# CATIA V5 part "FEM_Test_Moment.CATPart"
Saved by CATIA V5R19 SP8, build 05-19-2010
Part number: Part1
Material "Stahl": density 7860 kg/m3, Young's modulus 1e+16 Pa, Poisson ratio 0.266, thermal expansion 1.17e-05 1/K
Bounding box of the stored display mesh (mm): x -5 to 5, y 0 to 100, z -60 to 60
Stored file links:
  C:\Users\Bernd\Desktop\FEM_Test_Moment.CATPart
  C:\CATIA_V5_R19\Dassault Systemes\B19\intel_a\startup\materials\German\Catalog.CATMaterial
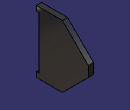
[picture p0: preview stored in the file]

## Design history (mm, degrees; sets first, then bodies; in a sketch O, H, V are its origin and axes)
AxisSystem1: origin (0, 0, 0), X (1, 0, 0), Y (0, 1, 0), Z (0, 0, 1)
Body1 (main body), material "Stahl"
  Sketch1 on YZ plane of AxisSystem1, origin (0, 0, 0), H (0, 1, 0), V (0, 0, 1)
    point P1 (50, 0)
    line L1 (100, 60) -> (100, -60)
    line L2 (100, -60) -> (0, -60)
    line L3 (0, -60) -> (0, 60)
    line L4 (0, 60) -> (100, 60)
    point P5 (0, 60)
    length L4 = 100
    length L1 = 120
    vertical: L1 V, L3 V
    horizontal: L2 H, L4 H
    equidistance: L1 L3 P1, L2 L4 P1
    coincidence: P5 V, P1 H
  Pad1: profile Sketch1, direction (1, 0, 0), length 5, mirrored extent
  Chamfer1: length 50, angle 45, on edge [face of Pad1 from Sketch1.L4 | face of Pad1 from Sketch1.L1]; edge [face of Pad1 from Sketch1.L1 | face of Pad1 from Sketch1.L2]
  Sketch2 on YZ plane of AxisSystem1, origin (0, 0, 0), H (0, 1, 0), V (0, 0, 1)
    point P1 (2.5, 0)
    line L1 (5, 50) -> (5, -50)
    line L2 (5, -50) -> (0, -50)
    line L3 (0, -50) -> (0, 50)
    line L4 (0, 50) -> (5, 50)
    point P5 (0, 50)
    length L3 = 100
    length L4 = 5
    vertical: L1 V, L3 V
    horizontal: L2 H, L4 H
    equidistance: L1 L3 P1, L2 L4 P1
    coincidence: P5 V, P1 H
  Pocket1: profile Sketch2, direction (-1, 0, 0), through (limit type 3), opposite side through (limit type 3)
